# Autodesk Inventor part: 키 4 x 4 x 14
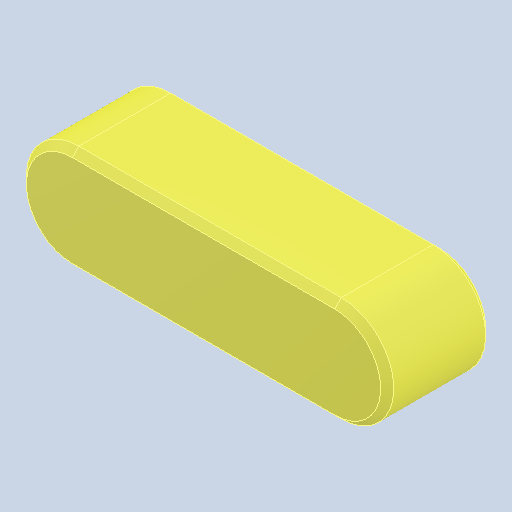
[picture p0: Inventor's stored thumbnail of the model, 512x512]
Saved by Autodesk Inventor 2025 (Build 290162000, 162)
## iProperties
Created: 2024-07
Part Number: 키 4 x 4 x 14
Material: 강철, 연강
Description: 키 및 해당 키홈
Document SubType Name: Modeling
Designer: SAMSUNG
Density: 7.85 g/cm^3
Appearance: 기본값
Author: jhkim
Sending System: Autodesk Inventor 2025
Preprocessor: ST-DEVELOPER v20
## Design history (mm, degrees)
feature "Solid1"
node "솔리드1"
